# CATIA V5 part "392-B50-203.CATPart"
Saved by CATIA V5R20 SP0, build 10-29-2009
Part number: 392-B50-203
Definition: NONE
Nomenclature: 392-B50-203
Source: Unknown
Description: 392-B50-203
Bounding box of the stored display mesh (mm): x 0 to 203, y -24.558 to 24.558, z -24.4 to 24.222
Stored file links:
  C:\Users\Utente\Desktop\IO LAVORO\3D X SITO CF\X SITO\3D files 392B\392-B50-203.CATPart
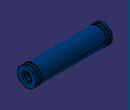
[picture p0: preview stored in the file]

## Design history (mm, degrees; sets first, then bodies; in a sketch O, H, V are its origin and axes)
Body1 "392-B50-203" (main body)
  Solid1: solid without history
